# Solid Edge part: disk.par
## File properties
Author: Binay
Template: sync ansi part.par
Last saved by: TIET
Revision: 6
Application: Solid Edge
Accuracy: 0.990
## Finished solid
Body 1: solid body, 19 faces, 50 edges, 32 vertices.
  Faces by surface: plane 10, cylinder 9
  Edges by curve: line 32, circle 18
Bounding box of the edges (mm): 50.402 x 50.402 x 3.175, from (2.9188, 47.4242, -1.5875) to (53.3204, 97.8258, 1.5875).
Cylindrical faces by radius (mm): R3.175 x4, R12.7 x1, R25.4 x4
Planar faces by outward normal: +x 2, +y 2, +z 1, -x 2, -y 2, -z 1
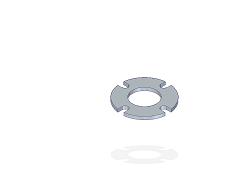
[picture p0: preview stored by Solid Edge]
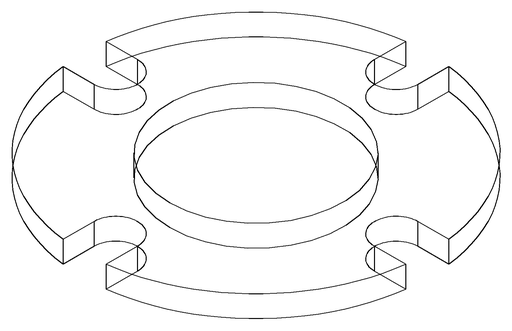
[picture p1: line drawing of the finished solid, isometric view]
